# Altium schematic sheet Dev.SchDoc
size 292 x 193 mm; Author: Power Lin; DocumentNumber: 3; SheetNumber: 3; SheetTotal: 4; Website: wiki-power.com
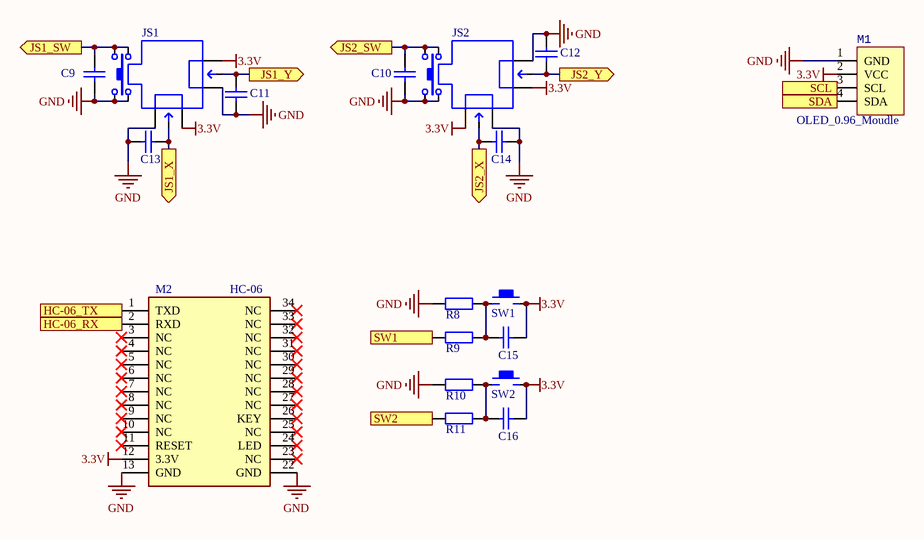
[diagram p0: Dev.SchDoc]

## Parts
C9  220pF  [CAP-0603]  (value not drawn)
C10  220pF  [CAP-0603]  (value not drawn)
C11  220pF  [CAP-0603]  (value not drawn)
C12  220pF  [CAP-0603]  (value not drawn)
C13  220pF  [CAP-0603]  (value not drawn)
C14  220pF  [CAP-0603]  (value not drawn)
C15  100nF  [CAP-0603]  (value not drawn)
C16  100nF  [CAP-0603]  (value not drawn)
JS1  JoyStick  [JoyStick]  (value not drawn)
JS2  JoyStick  [JoyStick]  (value not drawn)
M1  OLED_0.96_Moudle  [OLED_0.96_Moudle]
M2  HC-06  [HC-05/06/08V15]
R8  4.7k  [R-0603]  (value not drawn)
R9  1k  [R-0603]  (value not drawn)
R10  4.7k  [R-0603]  (value not drawn)
R11  1k  [R-0603]  (value not drawn)
SW1  KEY  [KEY_12*12*7.3]  (value not drawn)
SW2  KEY  [KEY_12*12*7.3]  (value not drawn)

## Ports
HC-06_RX (in), HC-06_TX (out), JS1_SW (out), JS1_X (out), JS1_Y (out), JS2_SW (out), JS2_X (out), JS2_Y (out), SCL (out), SDA (out), SW1 (out), SW2 (out)

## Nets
3.3V: C15.2 C16.2 JS1.3 JS1.6 JS2.1 JS2.4 M1.2(VCC) M2.12(3.3V) SW1.2 SW2.2
GND: C9.1 C10.1 C11.1 C12.2 C13.2 C14.1 JS1.1 JS1.4 JS1.8 JS1.10 JS2.3 JS2.6 JS2.8 JS2.10 M1.1(GND) M2.13(GND) M2.22(GND) R8.1 R10.1
HC-06_RX: M2.2(RXD) ; port HC-06_RX
HC-06_TX: M2.1(TXD) ; port HC-06_TX
JS1_SW: C9.2 JS1.7 JS1.9 ; port JS1_SW
JS1_X: C13.1 JS1.2 ; port JS1_X
JS1_Y: C11.2 JS1.5 ; port JS1_Y
JS2_SW: C10.2 JS2.7 JS2.9 ; port JS2_SW
JS2_X: C14.2 JS2.2 ; port JS2_X
JS2_Y: C12.1 JS2.5 ; port JS2_Y
SCL: M1.3(SCL) ; port SCL
SDA: M1.4(SDA) ; port SDA
SW1: R9.1 ; port SW1
SW2: R11.1 ; port SW2
NetC15_1: C15.1 R8.2 R9.2 SW1.1
NetC16_1: C16.1 R10.2 R11.2 SW2.1

Not connected (* = marked no-connect by the designer): M2 3(NC)* 4(NC)* 5(NC)* 6(NC)* 7(NC)* 8(NC)* 9(NC)* 10(NC)* 11(RESET)* 23(NC)* 24(LED)* 25(NC)* 26(KEY)* 27(NC)* 28(NC)* 29(NC)* 30(NC)* 31(NC)* 32(NC)* 33(NC)* 34(NC)*

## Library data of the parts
C9-C16 = CAP: 贴片电容
JS1 JS2 = JoyStick: 摇杆
M1 = OLED_0.96_Moudle: OLED 屏
M2 = HC-05/06: HC05/06 蓝牙模块（贴片）; Manufacturer_Name: FTDI Chip; Manufacturer_Part_Number: FT232RL
R8-R11 = RES: 贴片电阻
SW1 SW2 = KEY: 按键开关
